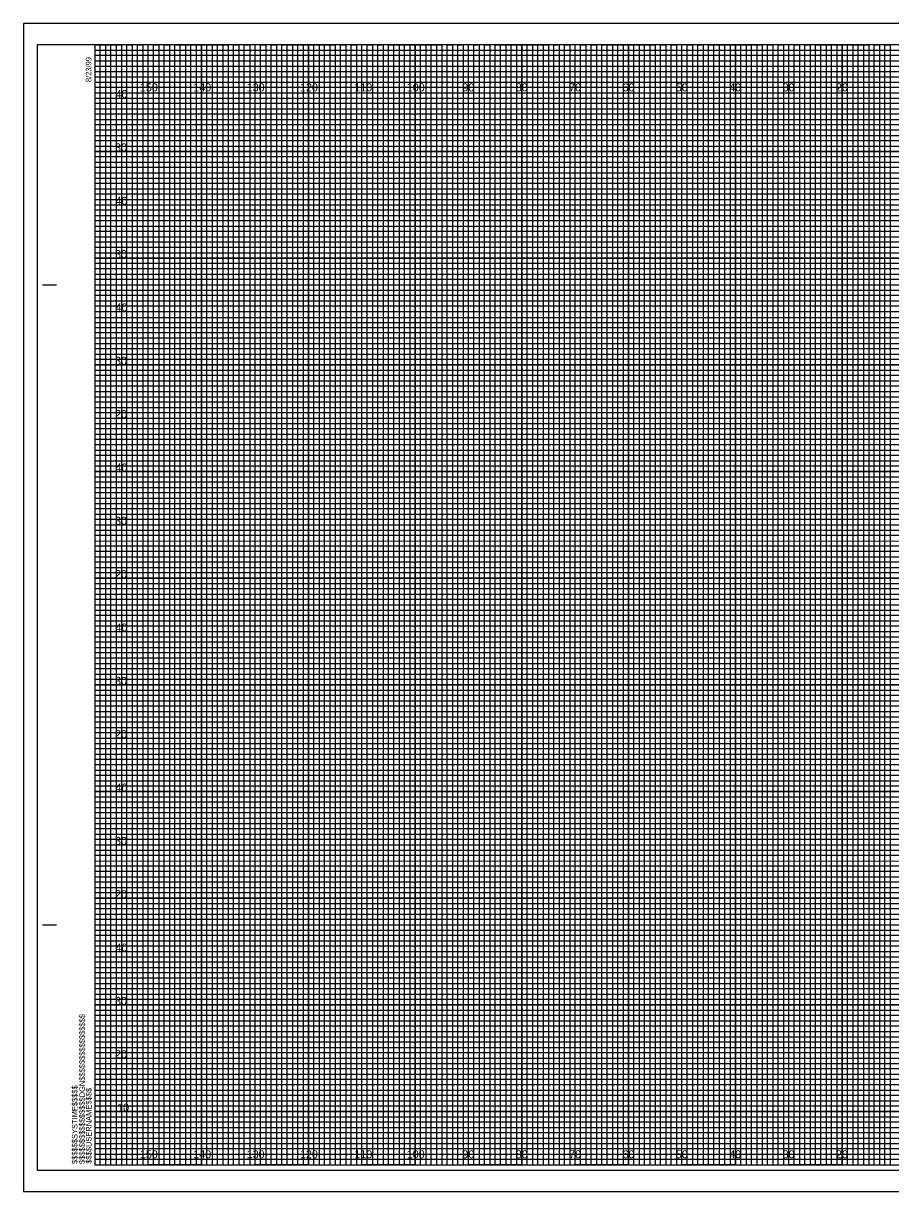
# Model space of a CAD drawing. Extents: x -13 to 323, y 435 to 654.
# Drawn here: x -13.4 to 149.1, y 435 to 654 of the extents above; entities that cross this region are included whole.
import ezdxf

# ---------------------------------------------------------------- set-up
doc = ezdxf.new("R2010")
doc.units = 0
for name, color, linetype in [('Exist Cross Section Cell', 7, 'Continuous'), ('Exist XS Center Line Elevation Label', 7, 'Continuous'), ('Exist XS Ground Line', 7, 'Continuous'), ('Prop XS DDE Slope Text', 7, 'Continuous'), ('Prop XS Earthwork Shape', 7, 'Continuous'), ('Prop XS Finish Grade', 7, 'Continuous'), ('Prop XS Finish Grade Earthwork', 7, 'Continuous'), ('Prop XS Label Text', 7, 'Continuous'), ('Prop XS SE Text', 7, 'Continuous'), ('Sheet DOT Grid CELL', 7, 'Continuous'), ('Sheet Plot Border Inside CELL', 7, 'Continuous')]:
    doc.layers.add(name, color=color, linetype=linetype)

msp = doc.modelspace()

# ---------------------------------------------------------------- linework, layer by layer
at = {"layer": 'Exist XS Center Line Elevation Label'}
for points in [[(0, 650), (5, 650), (5, 440), (15, 440), (15, 650), (25, 650), (25, 440), (35, 440), (35, 650), (45, 650), (45, 440), (55, 440), (55, 650), (65, 650), (65, 440), (75, 440), (75, 650), (85, 650), (85, 440), (95, 440), (95, 650), (105, 650), (105, 440), (115, 440), (115, 650), (125, 650), (125, 440), (135, 440), (135, 650), (145, 650), (145, 440), (155, 440)], [(0, 645), (275, 645)], [(0, 625), (320, 625), (320, 635), (0, 635)], [(0, 605), (320, 605), (320, 615), (0, 615)], [(0, 585), (320, 585), (320, 595), (0, 595)], [(0, 565), (320, 565), (320, 575), (0, 575)], [(0, 545), (320, 545), (320, 555), (0, 555)], [(0, 525), (320, 525), (320, 535), (0, 535)], [(0, 505), (320, 505), (320, 515), (0, 515)], [(0, 485), (320, 485), (320, 495), (0, 495)], [(0, 465), (320, 465), (320, 475), (0, 475)], [(0, 445), (320, 445), (320, 455), (0, 455)]]:
    msp.add_lwpolyline(points, dxfattribs=at)
at = {"layer": 'Exist XS Ground Line'}
for p, q in [((10, 650), (0, 650)), ((10, 440), (10, 650)), ((30, 650), (20, 650)), ((20, 650), (20, 440)), ((30, 440), (30, 650)), ((50, 650), (40, 650)), ((40, 650), (40, 440)), ((50, 440), (50, 650)), ((70, 650), (60, 650)), ((60, 650), (60, 440)), ((70, 440), (70, 650)), ((90, 650), (80, 650)), ((80, 650), (80, 440)), ((90, 440), (90, 650)), ((110, 650), (100, 650)), ((100, 650), (100, 440)), ((110, 440), (110, 650)), ((130, 650), (120, 650)), ((120, 650), (120, 440)), ((130, 440), (130, 650)), ((150, 650), (140, 650)), ((140, 650), (140, 440)), ((20, 440), (10, 440)), ((40, 440), (30, 440)), ((60, 440), (50, 440)), ((80, 440), (70, 440)), ((100, 440), (90, 440)), ((120, 440), (110, 440)), ((140, 440), (130, 440))]:
    msp.add_line(p, q, dxfattribs=at)
for points in [[(0, 640), (320, 640), (320, 630), (0, 630)], [(0, 620), (320, 620), (320, 610), (0, 610)], [(0, 600), (320, 600), (320, 590), (0, 590)], [(0, 580), (320, 580), (320, 570), (0, 570)], [(0, 560), (320, 560), (320, 550), (0, 550)], [(0, 540), (320, 540), (320, 530), (0, 530)], [(0, 520), (320, 520), (320, 510), (0, 510)], [(0, 500), (320, 500), (320, 490), (0, 490)], [(0, 480), (320, 480), (320, 470), (0, 470)], [(0, 460), (320, 460), (320, 450), (0, 450)]]:
    msp.add_lwpolyline(points, dxfattribs=at)
at = {"layer": 'Prop XS DDE Slope Text'}
msp.add_lwpolyline([(-13.4, 435), (323.3, 435), (323.3, 654), (-13.4, 654)], close=True, dxfattribs=at)
at = {"layer": 'Prop XS Earthwork Shape'}
for p, q in [((0, 649), (260, 649)), ((260, 647.98), (0, 647.98)), ((0, 647.98), (0, 647)), ((0, 647), (260, 647)), ((260, 645.89), (0, 645.89)), ((0, 645.89), (0, 644)), ((0, 644), (320, 644))]:
    msp.add_line(p, q, dxfattribs=at)
for points in [[(0, 643), (270, 643), (320, 643), (320, 642), (0, 642)], [(0, 641), (320, 641), (320, 639), (0, 639)], [(0, 638), (320, 638), (320, 637), (0, 636.98)], [(0, 636), (320, 636), (320, 634), (0, 634)], [(0, 633), (320, 633), (320, 632), (0, 632)], [(0, 631), (320, 631), (320, 629), (0, 629)], [(0, 628), (320, 628), (320, 627), (0, 627)], [(0, 626), (320, 626), (320, 624), (0, 624)], [(0, 623), (320, 623), (320, 622), (0, 622)], [(0, 621), (320, 621), (320, 619), (0, 619)], [(0, 618), (320, 618), (320, 617), (0, 617)], [(0, 616), (320, 616), (320, 613.95), (320, 613), (320, 612), (0, 612)], [(0, 614), (320, 614), (320, 613), (0, 613)], [(0, 611), (320, 611), (320, 609), (0, 609.03)], [(0, 609.03), (320, 609), (320, 608), (0, 608)], [(0, 607), (320, 607), (320, 606), (0, 606)], [(0, 604), (320, 604), (320, 603), (0, 603)], [(0, 602), (320, 602), (320, 601), (0, 601)], [(-0.07, 598.89), (320, 598.89), (320, 597.88), (-0.07, 597.88)], [(0, 597), (320, 597), (320, 596), (0, 596)], [(0, 594), (320, 594), (320, 593), (0, 593)], [(0, 592), (320, 592), (320, 591), (0, 591)], [(0, 589), (320, 589), (320, 588), (0, 588)], [(0, 587), (320, 587), (320, 586), (0, 586)], [(0, 584), (320, 584), (320, 583), (0, 583)], [(0, 582), (320, 582), (320, 581), (0, 581)], [(0, 579), (320, 579), (319.99, 577.98), (0, 578)], [(0, 577), (320, 577), (320, 576), (0, 576)], [(0, 574), (320, 574), (320, 573), (0, 573)], [(0, 572), (320, 572), (320, 571), (0, 571)], [(0, 569), (320, 569), (320, 568), (0, 568)], [(0, 567), (320, 567), (320, 566), (0, 566)], [(0, 564), (320, 564), (320, 563), (0, 563)], [(0, 562), (320, 562), (320, 561), (0, 561)], [(0, 559), (320, 559), (320, 558), (0, 558)], [(0, 556.99), (320.07, 556.91), (320, 556), (0, 556)], [(0, 554), (320, 554), (320, 553), (0, 553)], [(0, 552), (320, 552), (320, 551), (0, 551)], [(0, 549), (320, 549), (320, 548), (0, 548)], [(0, 547), (320, 547), (320, 546), (0, 546)], [(0, 544), (320, 544), (320, 543), (0, 543)], [(0, 542), (320, 542), (320, 541), (0, 541)], [(0, 539), (320, 539), (320, 538), (0, 538)], [(0, 537), (320, 537), (320, 536), (0, 536)], [(0, 534), (320, 534), (320, 533), (0, 533)], [(0, 532), (320, 532), (320, 531), (0, 531)], [(0, 529), (320, 529), (320, 528), (0, 528)], [(0, 527), (320, 527), (320, 526), (0, 526)], [(0, 524), (320, 524), (320, 523), (0, 523)], [(0, 522), (320, 522), (320, 521), (0, 521)], [(0, 519), (320, 519), (319.99, 517.98), (0, 518)], [(0, 517), (320, 517), (320, 516), (0, 516)], [(0, 514), (320, 514), (320, 513), (0, 513)], [(0, 512), (320, 512), (320, 511), (0, 511)], [(0, 509), (320, 509), (320, 508), (0, 508)], [(0, 507), (320, 507), (320, 506), (0, 506)], [(0, 504), (320, 504), (320, 503), (0, 503)], [(0, 502), (320, 502), (320, 501), (0, 501)], [(0, 499), (320, 499), (320, 498), (0, 498)], [(0, 496.99), (320.07, 496.91), (320, 496), (0, 496)], [(0, 494), (320, 494), (320, 493), (0, 493)], [(0, 492), (320, 492), (320, 491), (0, 491)], [(0, 489), (320, 489), (320, 488), (0, 488)], [(0, 487), (320, 487), (320, 486), (0, 486)], [(0, 484), (320, 484), (320, 483), (0, 483)], [(0, 482), (320, 482), (320, 481), (0, 481)], [(0, 479), (320, 479), (320, 478), (0, 478)], [(0, 477), (320, 477), (320, 476), (0, 476)], [(0, 474), (320, 474), (320, 473), (0, 473)], [(0, 472), (320, 472), (320, 471), (0, 471)], [(0, 469), (320, 469), (320, 468), (0, 468)], [(0, 467), (320, 467), (320, 466), (0, 466)], [(0, 464), (320, 464), (320, 463), (0, 463)], [(0, 462), (320, 462), (320, 461), (0, 461)], [(0, 459), (320, 459), (320, 458), (0, 458)], [(0, 457), (320, 457), (320, 456), (0, 456)], [(0, 454), (320, 454), (320, 453), (0, 453)], [(0, 452), (320, 452), (320, 451), (0, 451)], [(0, 449), (320, 449), (320, 448), (0, 448)], [(0, 447), (320, 447), (320, 446), (0, 446)], [(0, 444), (320, 444), (320, 443), (0, 443)], [(0, 442), (320, 442), (320, 441), (0, 441)]]:
    msp.add_lwpolyline(points, dxfattribs=at)
at = {"layer": 'Prop XS Finish Grade Earthwork'}
for p, q in [((323.3, 654), (-13.4, 654)), ((-13.4, 654), (-13.4, 435)), ((-13.4, 435), (323.3, 435))]:
    msp.add_line(p, q, dxfattribs=at)
at = {"layer": 'Prop XS Label Text'}
for points in [[(0, 440), (1, 440), (1, 650), (2, 650), (2, 440)], [(2, 440), (3, 440), (3, 650), (4, 650), (4, 440)], [(5, 440), (6, 440), (6, 650), (7, 650), (7, 440)], [(7, 440), (8, 440), (8, 650), (9, 650), (9, 440)], [(10, 440), (11, 440), (11, 650), (12, 650), (12, 440)], [(12, 440), (13, 440), (13, 650), (14, 650), (14, 440)], [(15, 440), (16, 440), (16, 650), (17, 650), (17, 440)], [(17, 440), (18, 440), (18, 650), (19, 650), (19, 440)], [(20, 440), (21, 440), (21, 650), (22, 650), (22, 440)], [(22, 440), (23, 440), (23, 650), (24, 650), (24, 440)], [(25, 440), (26, 440), (26, 650), (27, 650), (27, 440)], [(27, 440), (28, 440), (28, 650), (29, 650), (29, 440)], [(30, 440), (31, 440), (31, 650), (32, 650), (32, 440)], [(32, 440), (33, 440), (33, 650), (34, 650), (34, 440)], [(35, 440), (36, 440), (36, 650), (37, 650), (37, 440)], [(37, 440), (38, 440), (38, 650), (39, 650), (39, 440)], [(40, 440), (41, 440), (41, 650), (42, 650), (42, 440)], [(42, 440), (43, 440), (43, 650), (44, 650), (44, 440)], [(45, 440), (46, 440), (46, 650), (47, 650), (47, 440)], [(47, 440), (48, 440), (48, 650), (49, 650), (49, 440)], [(50, 440), (51, 440), (51, 650), (52, 650), (52, 440)], [(52, 440), (53, 440), (53, 650), (54, 650), (54, 440)], [(55, 440), (56, 440), (56, 650), (57, 650), (57, 440)], [(57, 440), (58, 440), (58, 650), (59, 650), (59, 440)], [(60, 440), (61, 440), (61, 650), (62, 650), (62, 440)], [(62, 440), (63, 440), (63, 650), (64, 650), (64, 440)], [(65, 440), (66, 440), (66, 650), (67, 650), (67, 440)], [(67, 440), (68, 440), (68, 650), (69, 650), (69, 440)], [(70, 440), (71, 440), (71, 650), (72, 650), (72, 440)], [(72, 440), (73, 440), (73, 650), (74, 650), (74, 440)], [(75, 440), (76, 440), (76, 650), (77, 650), (77, 440)], [(77, 440), (78, 440), (78, 650), (79, 650), (79, 440)], [(80, 440), (81, 440), (81, 650), (82, 650), (82, 440)], [(82, 440), (83, 440), (83, 650), (84, 650), (84, 440)], [(85, 440), (86, 440), (86, 650), (87, 650), (87, 440)], [(87, 440), (88, 440), (88, 650), (89, 650), (89, 440)], [(90, 440), (91, 440), (91, 650), (92, 650), (92, 440)], [(92, 440), (93, 440), (93, 650), (94, 650), (94, 440)], [(95, 440), (96, 440), (96, 650), (97, 650), (97, 440)], [(97, 440), (98, 440), (98, 650), (99, 650), (99, 440)], [(100, 440), (101, 440), (101, 650), (102, 650), (102, 440)], [(102, 440), (103, 440), (103, 650), (104, 650), (104, 440)], [(105, 440), (106, 440), (106, 650), (107, 650), (107, 440)], [(107, 440), (108, 440), (108, 650), (109, 650), (109, 440)], [(110, 440), (111, 440), (111, 650), (112, 650), (112, 440)], [(112, 440), (113, 440), (113, 650), (114, 650), (114, 440)], [(115, 440), (116, 440), (116, 650), (117, 650), (117, 440)], [(117, 440), (118, 440), (118, 650), (119, 650), (119, 440)], [(120, 440), (121, 440), (121, 650), (122, 650), (122, 440)], [(122, 440), (123, 440), (123, 650), (124, 650), (124, 440)], [(125, 440), (126, 440), (126, 650), (127, 650), (127, 440)], [(127, 440), (128, 440), (128, 650), (129, 650), (129, 440)], [(130, 440), (131, 440), (131, 650), (132, 650), (132, 440)], [(132, 440), (133, 440), (133, 650), (134, 650), (134, 440)], [(135, 440), (136, 440), (136, 650), (137, 650), (137, 440)], [(137, 440), (138, 440), (138, 650), (139, 650), (139, 440)], [(140, 440), (141, 440), (141, 650), (142, 650), (142, 440)], [(142, 440), (143, 440), (143, 650), (144, 650), (144, 440)], [(145, 440), (146, 440), (146, 650), (147, 650), (147, 440)], [(147, 440), (148, 440), (148, 650), (149, 650), (149, 440)]]:
    msp.add_lwpolyline(points, dxfattribs=at)
at = {"layer": 'Prop XS SE Text'}
for p, q in [((-9.8, 605), (-7.3, 605)), ((-9.7, 605), (-7.2, 605)), ((-9.8, 485), (-7.3, 485)), ((-9.7, 485), (-7.2, 485)), ((0, 440), (0, 440)), ((0, 440), (0, 440)), ((0, 440), (0, 440)), ((0, 440), (0, 440)), ((0, 440), (0, 440)), ((0, 440), (0, 440)), ((0, 440), (0, 440))]:
    msp.add_line(p, q, dxfattribs=at)
msp.add_lwpolyline([(320, 650), (0, 650), (0, 440), (320, 440)], close=True, dxfattribs=at)
at = {"layer": 'Sheet DOT Grid CELL'}
for p, q in [((10, 440), (10, 650)), ((20, 440), (20, 650)), ((30, 440), (30, 650)), ((40, 440), (40, 650)), ((50, 440), (50, 650)), ((60, 440), (60, 650)), ((70, 440), (70, 650)), ((80, 440), (80, 650)), ((90, 440), (90, 650)), ((100, 440), (100, 650)), ((110, 440), (110, 650)), ((120, 440), (120, 650)), ((130, 440), (130, 650)), ((140, 440), (140, 650)), ((0, 640), (320, 640)), ((0, 630), (320, 630)), ((0, 620), (320, 620)), ((0, 610), (320, 610)), ((0, 600), (320, 600)), ((0, 590), (320, 590)), ((0, 580), (320, 580)), ((0, 570), (320, 570)), ((0, 560), (320, 560)), ((0, 550), (320, 550)), ((0, 540), (320, 540)), ((0, 530), (320, 530)), ((0, 520), (320, 520)), ((0, 510), (320, 510)), ((0, 500), (320, 500)), ((0, 490), (320, 490)), ((0, 480), (320, 480)), ((0, 470), (320, 470)), ((0, 460), (320, 460)), ((0, 450), (320, 450))]:
    msp.add_line(p, q, dxfattribs=at)
at = {"layer": 'Sheet Plot Border Inside CELL'}
msp.add_lwpolyline([(-10.8, 439), (322.4, 439), (322.4, 650), (-10.8, 650)], close=True, dxfattribs=at)

# ---------------------------------------------------------------- texts
at = {"layer": 'Exist Cross Section Cell'}
for s, p in [('150', (8.44, 641.25)), ('140', (18.44, 641.25)), ('130', (28.44, 641.25)), ('120', (38.44, 641.25)), ('110', (48.62, 641.25)), ('100', (58.44, 641.25)), ('90', (68.86, 641.25)), ('80', (78.86, 641.25)), ('70', (88.86, 641.25)), ('60', (98.86, 641.25)), ('50', (108.86, 641.25)), ('40', (118.86, 641.25)), ('30', (128.86, 641.25)), ('20', (138.86, 641.25)), ('150', (8.44, 441.25)), ('140', (18.44, 441.25)), ('130', (28.44, 441.25)), ('120', (38.44, 441.25)), ('110', (48.62, 441.25)), ('100', (58.44, 441.25)), ('90', (68.86, 441.25)), ('80', (78.86, 441.25)), ('70', (88.86, 441.25)), ('60', (98.86, 441.25)), ('50', (108.86, 441.25)), ('40', (118.86, 441.25)), ('30', (128.86, 441.25)), ('20', (138.86, 441.25))]:
    msp.add_text(s, height=1.5, dxfattribs=at).set_placement(p)
at = {"layer": 'Prop XS Finish Grade'}
for s, p in [('40', (3.87, 640)), ('30', (3.78, 630)), ('40', (3.87, 620)), ('30', (3.78, 610)), ('40', (3.87, 600)), ('30', (3.78, 590)), ('20', (3.8, 580)), ('40', (3.87, 570)), ('30', (3.78, 560)), ('20', (3.8, 550)), ('40', (3.87, 540)), ('30', (3.78, 530)), ('20', (3.8, 520)), ('40', (3.87, 510)), ('30', (3.78, 500)), ('20', (3.8, 490)), ('40', (3.87, 480)), ('30', (3.78, 470)), ('20', (3.8, 460)), ('10', (4.17, 450))]:
    msp.add_text(s, height=1.5, dxfattribs=at).set_placement(p)
at = {"layer": 'Prop XS SE Text'}
for s, p in [('8/23/99', (-0.65, 643)), ('$$$$$$$$$$$$$$$$DGN$$$$$$$$$$$$$$$$', (-1.88, 440.18)), ('$$$$$$SYSTIME$$$$$', (-3.26, 440.18)), ('$$$$USERNAME$$$$', (-0.62, 440.23))]:
    msp.add_text(s, height=1.05, rotation=90, dxfattribs=at).set_placement(p)

doc.saveas('drawing.dxf')
